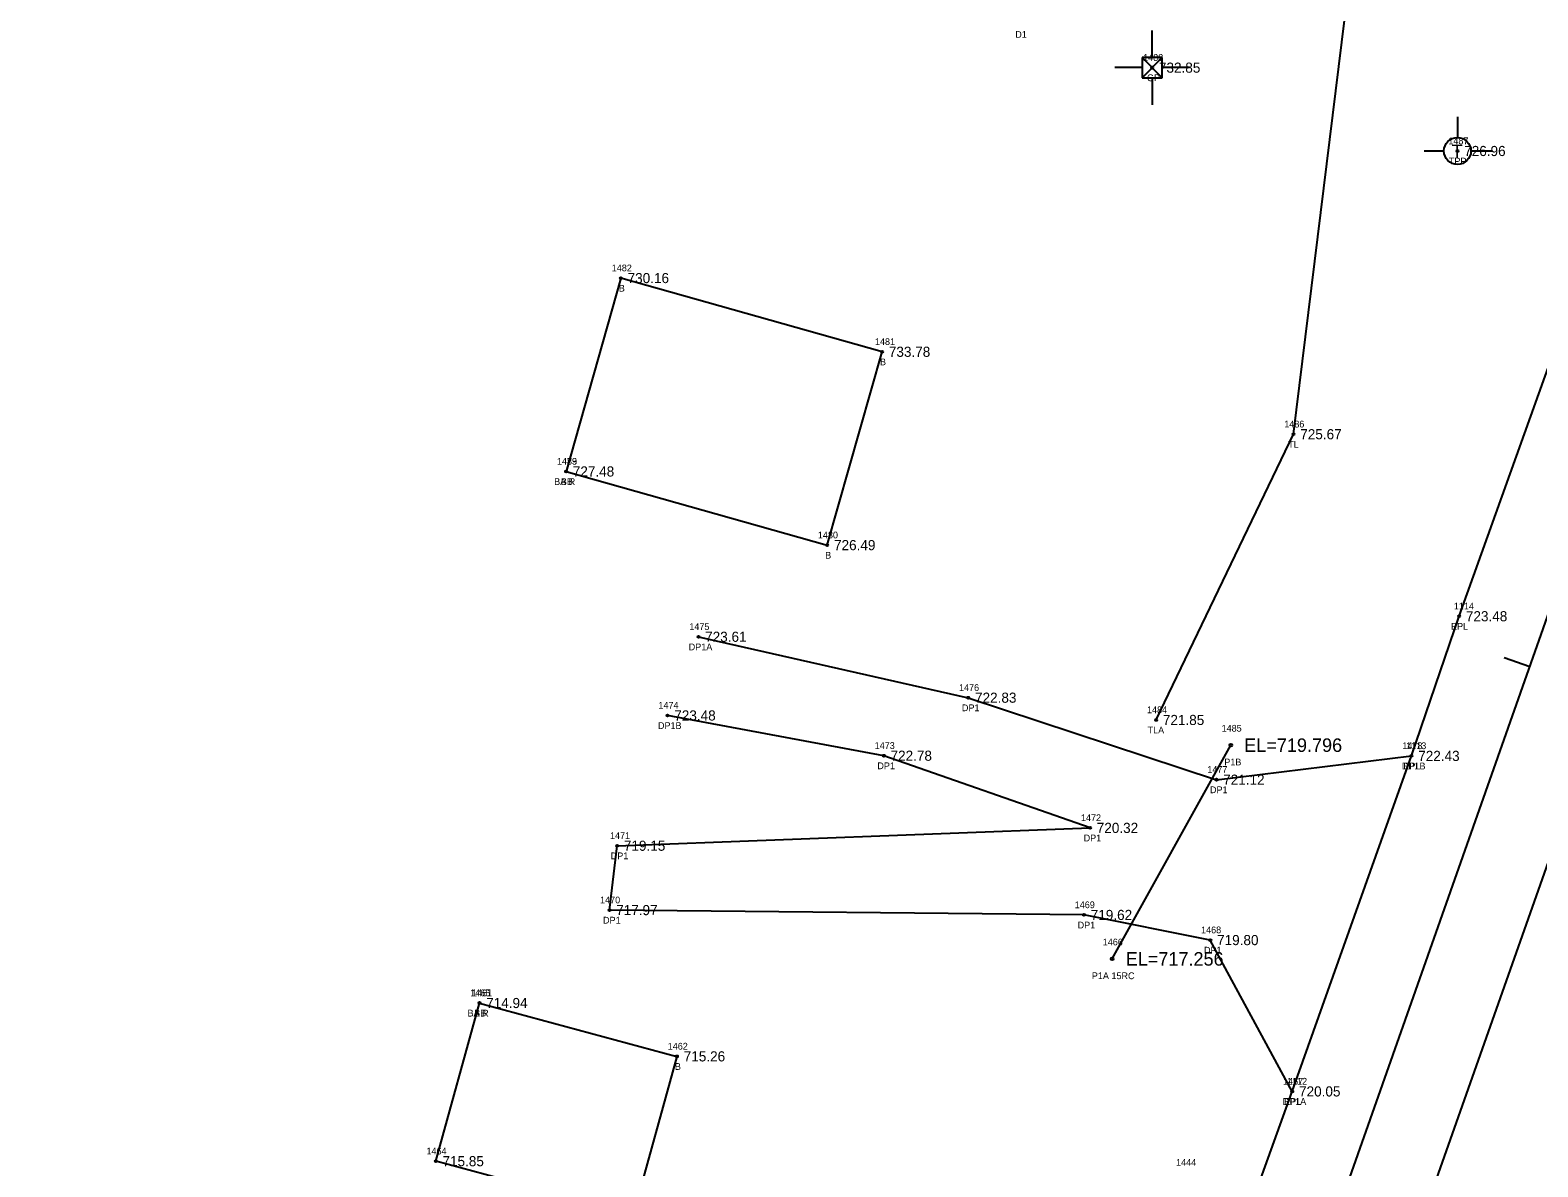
# Model space of a CAD drawing. Extents: x 1736563 to 1738032, y 1150548 to 1154248.
# Drawn here: x 1737284.7 to 1737508, y 1152859 to 1153027.3 of the extents above; entities that cross this region are included whole.
import ezdxf

# ---------------------------------------------------------------- set-up
doc = ezdxf.new("R2010")
doc.units = 0
for name, color, linetype in [('RD_EX_Bldg', 7, 'Continuous'), ('RD_EX_Bldg_txCode', 7, 'Continuous'), ('RD_EX_DR_Pipe', 7, 'Continuous'), ('RD_EX_DR_Pipe_txCode', 7, 'Continuous'), ('RD_EX_Driveway', 7, 'Continuous'), ('RD_EX_Driveway_txCode', 7, 'Continuous'), ('RD_EX_GuardRail_txCode', 7, 'Continuous'), ('RD_EX_Road', 7, 'Continuous'), ('RD_EX_Road_txCode', 7, 'Continuous'), ('RD_EX_TX_Bldg_ELEV', 7, 'Continuous'), ('RD_EX_TX_Driveway_ELEV', 7, 'Continuous'), ('RD_EX_TX_Road_ELEV', 7, 'Continuous'), ('RD_EX_TX_UT_ELEV', 7, 'Continuous'), ('RD_EX_TX_VEG_ELEV', 7, 'Continuous'), ('RD_EX_UT', 7, 'Continuous'), ('RD_EX_UT_txCode', 7, 'Continuous'), ('RD_EX_VEG', 7, 'Continuous'), ('RD_EX_VEG_txCode', 7, 'Continuous'), ('RD_HC_Cl', 7, 'Continuous'), ('RD_HC_Data_Tic', 7, 'Continuous'), ('RD_SMD_Locator', 7, 'Continuous'), ('RD_TX_Pipe_ElevEX', 7, 'Continuous')]:
    doc.layers.add(name, color=color, linetype=linetype)

msp = doc.modelspace()

# ---------------------------------------------------------------- linework, layer by layer
at = {"layer": 'RD_EX_Bldg'}
for points in [[(1737364.09, 1152961.99), (1737402.78, 1152951.08), (1737410.9, 1152979.71), (1737372.21, 1152990.62), (1737364.09, 1152961.99)], [(1737351.26, 1152883.28), (1737380.52, 1152875.38), (1737374.05, 1152851.97), (1737344.79, 1152859.86), (1737351.26, 1152883.28)]]:
    msp.add_lwpolyline(points, dxfattribs=at)
at = {"layer": 'RD_EX_DR_Pipe'}
msp.add_line((1737444.98, 1152889.81), (1737462.53, 1152921.46), dxfattribs=at)
at = {"layer": 'RD_EX_Driveway'}
for points in [[(1737383.69, 1152937.51), (1737423.66, 1152928.49), (1737460.41, 1152916.35), (1737489.3, 1152919.87)], [(1737471.65, 1152870.19), (1737459.51, 1152892.6), (1737440.8, 1152896.32), (1737370.52, 1152897.04), (1737371.66, 1152906.57), (1737441.69, 1152909.21), (1737411.15, 1152919.9), (1737379.12, 1152925.86)]]:
    msp.add_lwpolyline(points, dxfattribs=at)
at = {"layer": 'RD_EX_Road'}
for points in [[(1737441.53, 1152749.22), (1737453.38, 1152745.01), (1737485.9, 1152837.06), (1737519.36, 1152931.88), (1737528.68, 1152958.21), (1737543.28, 1152998.9), (1737552.4, 1153024.11), (1737569.73, 1153074.37)], [(1737441.53, 1152749.22), (1737430.41, 1152752.97), (1737462.49, 1152844.79), (1737471.65, 1152870.19), (1737489.3, 1152919.87), (1737496.36, 1152940.55), (1737529.37, 1153032.75)]]:
    msp.add_lwpolyline(points, dxfattribs=at)
at = {"layer": 'RD_EX_UT'}
for p, q in [((1737450.9, 1153023.28), (1737450.9, 1153027.28)), ((1737449.38, 1153021.82), (1737445.38, 1153021.82)), ((1737452.4, 1153023.28), (1737449.4, 1153020.28)), ((1737449.4, 1153023.28), (1737452.4, 1153020.28)), ((1737452.4, 1153023.28), (1737449.4, 1153023.28)), ((1737449.4, 1153023.28), (1737449.4, 1153020.28)), ((1737452.4, 1153020.28), (1737452.4, 1153023.28)), ((1737452.42, 1153021.84), (1737456.43, 1153021.84)), ((1737449.4, 1153020.28), (1737452.4, 1153020.28)), ((1737450.9, 1153020.28), (1737450.9, 1153016.28)), ((1737496.11, 1153014.51), (1737496.11, 1153011.44)), ((1737491.18, 1153009.45), (1737494.11, 1153009.45)), ((1737498.11, 1153009.45), (1737501.18, 1153009.45))]:
    msp.add_line(p, q, dxfattribs=at)
msp.add_circle((1737496.11, 1153009.44), 2, dxfattribs=at)
at = {"layer": 'RD_EX_VEG'}
msp.add_lwpolyline([(1737451.48, 1152925.19), (1737471.83, 1152967.5), (1737483.5, 1153062.03), (1737523.53, 1153143.47), (1737578.4, 1153225.34), (1737613.35, 1153318.74), (1737643.94, 1153407.18), (1737681, 1153500.22), (1737713.81, 1153596.51), (1737742.54, 1153686.46), (1737776.37, 1153777.24), (1737812.9, 1153871.37), (1737847.32, 1153964.45), (1737872.45, 1154065.49)], dxfattribs=at)
at = {"layer": 'RD_HC_Cl'}
msp.add_line((1736879.96, 1151154.46), (1737935.1, 1154148.31), dxfattribs=at)
at = {"layer": 'RD_HC_Data_Tic'}
msp.add_line((1737506.81, 1152933.07), (1737503.04, 1152934.4), dxfattribs=at)
at = {"layer": 'RD_SMD_Locator'}
for centre, radius in [((1737450.9, 1153021.78), 0.15), ((1737496.11, 1153009.44), 0.15), ((1737372.21, 1152990.62), 0.15), ((1737410.9, 1152979.71), 0.15), ((1737471.83, 1152967.5), 0.15), ((1737364.09, 1152961.99), 0.15), ((1737364.09, 1152961.99), 0.15), ((1737402.78, 1152951.08), 0.15), ((1737496.36, 1152940.55), 0.15), ((1737383.69, 1152937.51), 0.15), ((1737423.66, 1152928.49), 0.15), ((1737379.12, 1152925.86), 0.15), ((1737451.48, 1152925.19), 0.15), ((1737462.53, 1152921.46), 0.2), ((1737411.15, 1152919.9), 0.15), ((1737489.3, 1152919.87), 0.15), ((1737489.3, 1152919.87), 0.15), ((1737460.41, 1152916.35), 0.15), ((1737441.69, 1152909.21), 0.15), ((1737371.66, 1152906.57), 0.15), ((1737370.52, 1152897.04), 0.15), ((1737440.8, 1152896.32), 0.15), ((1737459.51, 1152892.6), 0.15), ((1737444.98, 1152889.81), 0.2), ((1737351.26, 1152883.28), 0.15), ((1737351.26, 1152883.28), 0.15), ((1737380.52, 1152875.38), 0.15), ((1737471.65, 1152870.19), 0.15), ((1737471.65, 1152870.19), 0.15), ((1737344.79, 1152859.86), 0.15)]:
    msp.add_circle(centre, radius, dxfattribs=at)

# ---------------------------------------------------------------- texts
at = {"layer": 'RD_EX_Bldg_txCode'}
for s, p in [('1482', (1737370.86, 1152991.62)), ('B', (1737371.9, 1152988.62)), ('1481', (1737409.84, 1152980.71)), ('B', (1737410.59, 1152977.71)), ('1479', (1737362.74, 1152962.99)), ('1483', (1737362.74, 1152962.99)), ('BA R', (1737362.33, 1152959.99)), ('BB', (1737363.31, 1152959.99)), ('1480', (1737401.39, 1152952.08)), ('B', (1737402.47, 1152949.08)), ('1465', (1737349.89, 1152884.28)), ('1461', (1737350.17, 1152884.28)), ('BA R', (1737349.5, 1152881.28)), ('BB', (1737350.48, 1152881.28)), ('1462', (1737379.15, 1152876.38)), ('B', (1737380.21, 1152873.38)), ('1464', (1737343.42, 1152860.86))]:
    msp.add_text(s, height=1, dxfattribs=at).set_placement(p)
at = {"layer": 'RD_EX_DR_Pipe_txCode'}
for s, p in [('1485', (1737461.18, 1152923.46)), ('P1B', (1737461.58, 1152918.46)), ('1466', (1737443.58, 1152891.81)), ('P1A 15RC', (1737441.97, 1152886.81))]:
    msp.add_text(s, height=1, dxfattribs=at).set_placement(p)
at = {"layer": 'RD_EX_Driveway_txCode'}
for s, p in [('D1', (1737430.62, 1153026.2)), ('1475', (1737382.35, 1152938.51)), ('DP1A', (1737382.26, 1152935.51)), ('1476', (1737422.29, 1152929.49)), ('1474', (1737377.77, 1152926.86)), ('DP1', (1737422.72, 1152926.49)), ('DP1B', (1737377.7, 1152923.86)), ('1473', (1737409.8, 1152920.9)), ('1478', (1737487.95, 1152920.87)), ('DP1', (1737410.2, 1152917.9)), ('DP1B', (1737487.88, 1152917.87)), ('1477', (1737459.06, 1152917.35)), ('DP1', (1737459.46, 1152914.35)), ('1472', (1737440.35, 1152910.21)), ('1471', (1737370.6, 1152907.57)), ('DP1', (1737440.75, 1152907.21)), ('DP1', (1737370.71, 1152904.57)), ('1470', (1737369.13, 1152898.04)), ('1469', (1737439.43, 1152897.32)), ('DP1', (1737369.57, 1152895.04)), ('DP1', (1737439.86, 1152894.32)), ('1468', (1737458.14, 1152893.6)), ('DP1', (1737458.57, 1152890.6)), ('1467', (1737470.28, 1152871.19)), ('DP1A', (1737470.22, 1152868.19))]:
    msp.add_text(s, height=1, dxfattribs=at).set_placement(p)
at = {"layer": 'RD_EX_GuardRail_txCode'}
msp.add_text('1444', height=1, dxfattribs=at).set_placement((1737454.44, 1152859.18))
at = {"layer": 'RD_EX_Road_txCode'}
for s, p in [('1114', (1737495.58, 1152941.55)), ('EPL', (1737495.16, 1152938.55)), ('1113', (1737488.52, 1152920.87)), ('EPL', (1737488.1, 1152917.87)), ('1112', (1737470.87, 1152871.19)), ('EPL', (1737470.45, 1152868.19))]:
    msp.add_text(s, height=1, dxfattribs=at).set_placement(p)
at = {"layer": 'RD_EX_TX_Bldg_ELEV'}
for s, p in [('730.16', (1737373.21, 1152989.87)), ('733.78', (1737411.9, 1152978.96)), ('727.48', (1737365.09, 1152961.24)), ('727.48', (1737365.09, 1152961.24)), ('726.49', (1737403.78, 1152950.33)), ('714.94', (1737352.26, 1152882.53)), ('714.94', (1737352.26, 1152882.53)), ('715.26', (1737381.52, 1152874.63)), ('715.85', (1737345.79, 1152859.11))]:
    msp.add_text(s, height=1.5, dxfattribs=at).set_placement(p)
at = {"layer": 'RD_EX_TX_Driveway_ELEV'}
for s, p in [('723.61', (1737384.69, 1152936.76)), ('722.83', (1737424.66, 1152927.74)), ('723.48', (1737380.12, 1152925.11)), ('722.78', (1737412.15, 1152919.15)), ('722.43', (1737490.3, 1152919.12)), ('721.12', (1737461.41, 1152915.6)), ('720.32', (1737442.69, 1152908.46)), ('719.15', (1737372.66, 1152905.82)), ('717.97', (1737371.52, 1152896.29)), ('719.62', (1737441.8, 1152895.57)), ('719.80', (1737460.51, 1152891.85)), ('720.05', (1737472.65, 1152869.44))]:
    msp.add_text(s, height=1.5, dxfattribs=at).set_placement(p)
at = {"layer": 'RD_EX_TX_Road_ELEV'}
for s, p in [('723.48', (1737497.36, 1152939.8)), ('722.43', (1737490.3, 1152919.12)), ('720.05', (1737472.65, 1152869.44))]:
    msp.add_text(s, height=1.5, dxfattribs=at).set_placement(p)
at = {"layer": 'RD_EX_TX_UT_ELEV'}
for s, p in [('732.85', (1737451.9, 1153021.03)), ('726.96', (1737497.11, 1153008.69))]:
    msp.add_text(s, height=1.5, dxfattribs=at).set_placement(p)
at = {"layer": 'RD_EX_TX_VEG_ELEV'}
for s, p in [('725.67', (1737472.83, 1152966.75)), ('721.85', (1737452.48, 1152924.44))]:
    msp.add_text(s, height=1.5, dxfattribs=at).set_placement(p)
at = {"layer": 'RD_EX_UT'}
msp.add_text('T', height=2, dxfattribs=at).set_placement((1737495.26, 1153008.39))
at = {"layer": 'RD_EX_UT_txCode'}
for s, p in [('1488', (1737449.56, 1153022.78)), ('GP', (1737450.12, 1153019.78)), ('1487', (1737494.76, 1153010.44)), ('TPP', (1737494.84, 1153007.44))]:
    msp.add_text(s, height=1, dxfattribs=at).set_placement(p)
at = {"layer": 'RD_EX_VEG_txCode'}
for s, p in [('1486', (1737470.46, 1152968.5)), ('TL', (1737471.05, 1152965.5)), ('1484', (1737450.13, 1152926.19)), ('TLA', (1737450.22, 1152923.19))]:
    msp.add_text(s, height=1, dxfattribs=at).set_placement(p)
at = {"layer": 'RD_TX_Pipe_ElevEX'}
for s, p in [('EL=719.796', (1737464.53, 1152920.46)), ('EL=717.256', (1737446.98, 1152888.81))]:
    msp.add_text(s, height=2, dxfattribs=at).set_placement(p)

doc.saveas('drawing.dxf')
